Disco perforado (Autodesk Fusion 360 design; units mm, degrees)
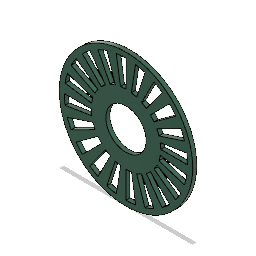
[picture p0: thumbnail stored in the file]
sketch "Sketch1"
  circle C1 centre (0, 0) radius 7.5
  circle C2 centre (0, 0) radius 25
  dimension "d1" diameter C1 = 15
  dimension "d2" diameter C2 = 50
extrude "Extrude1" new body sketch "Sketch1" blind 2
sketch "Sketch2"
  line L1 (25, 0) -> (0, 0)
  line L2 (25, 0) -> (0, 0)
  line L3 (25, 0) -> (0, 0)
  line L4 (24.6922, 3.9109) -> (0, 0)
  line L5 (23.7764, 7.7254) -> (0, 0)
  line L6 (20.2254, 14.6946) -> (0, 0)
  line L7 (22.2752, 11.3498) -> (0, 0)
  line L8 (23.7764, 7.7254) -> (0, 0)
  line L9 (14.6946, 20.2254) -> (0, 0)
  line L10 (17.6777, 17.6777) -> (0, 0)
  line L11 (20.2254, 14.6946) -> (0, 0)
  line L12 (7.7254, 23.7764) -> (0, 0)
  line L13 (11.3498, 22.2752) -> (0, 0)
  line L14 (14.6946, 20.2254) -> (0, 0)
  line L15 (0, 25) -> (0, 0)
  line L16 (3.9109, 24.6922) -> (0, 0)
  line L17 (7.7254, 23.7764) -> (0, 0)
  line L18 (0, 25) -> (0, 0)
  line L19 (-3.9109, 24.6922) -> (0, 0)
  line L20 (-7.7254, 23.7764) -> (0, 0)
  line L21 (-11.3498, 22.2752) -> (0, 0)
  line L22 (-14.6946, 20.2254) -> (0, 0)
  line L23 (-17.6777, 17.6777) -> (0, 0)
  line L24 (-20.2254, 14.6946) -> (0, 0)
  line L25 (-22.2752, 11.3498) -> (0, 0)
  line L26 (-23.7764, 7.7254) -> (0, 0)
  line L27 (-24.6922, 3.9109) -> (0, 0)
  line L28 (-25, 0) -> (0, 0)
  line L29 (-25, 0) -> (0, 0)
  line L30 (-24.6922, -3.9109) -> (0, 0)
  line L31 (-23.7764, -7.7254) -> (0, 0)
  line L32 (-22.2752, -11.3498) -> (0, 0)
  line L33 (-20.2254, -14.6946) -> (0, 0)
  line L34 (-17.6777, -17.6777) -> (0, 0)
  line L35 (-14.6946, -20.2254) -> (0, 0)
  line L36 (-11.3498, -22.2752) -> (0, 0)
  line L37 (-7.7254, -23.7764) -> (0, 0)
  line L38 (-3.9109, -24.6922) -> (0, 0)
  line L39 (0, -25) -> (0, 0)
  line L40 (0, -25) -> (0, 0)
  line L41 (3.9109, -24.6922) -> (0, 0)
  line L42 (7.7254, -23.7764) -> (0, 0)
  line L43 (11.3498, -22.2752) -> (0, 0)
  line L44 (14.6946, -20.2254) -> (0, 0)
  line L45 (17.6777, -17.6777) -> (0, 0)
  line L46 (20.2254, -14.6946) -> (0, 0)
  line L47 (22.2752, -11.3498) -> (0, 0)
  line L48 (23.7764, -7.7254) -> (0, 0)
  line L49 (24.6922, -3.9109) -> (0, 0)
  line L50 (25, 0) -> (0, 0)
  circle C1 centre (0, 0) radius 25
  arc A1 centre (0, 0) radius 23 clockwise from (22.7168, 3.598) to (23, 0)
  arc A2 centre (0, 0) radius 13 clockwise from (12.8399, 2.0336) to (13, 0)
  arc A3 centre (0, 0) radius 13 clockwise from (11.5831, 5.9019) to (12.3637, 4.0172)
  arc A4 centre (0, 0) radius 23 clockwise from (20.4932, 10.4418) to (21.8743, 7.1074)
  arc A5 centre (0, 0) radius 13 clockwise from (9.1924, 9.1924) to (10.5172, 7.6412)
  arc A6 centre (0, 0) radius 23 clockwise from (16.2635, 16.2635) to (18.6074, 13.5191)
  arc A7 centre (0, 0) radius 13 clockwise from (5.9019, 11.5831) to (7.6412, 10.5172)
  arc A8 centre (0, 0) radius 23 clockwise from (10.4418, 20.4932) to (13.5191, 18.6074)
  arc A9 centre (0, 0) radius 13 clockwise from (2.0336, 12.8399) to (4.0172, 12.3637)
  arc A10 centre (0, 0) radius 23 clockwise from (3.598, 22.7168) to (7.1074, 21.8743)
  arc A11 centre (0, 0) radius 13 clockwise from (-2.0336, 12.8399) to (0, 13)
  arc A12 centre (0, 0) radius 13 clockwise from (-5.9019, 11.5831) to (-4.0172, 12.3637)
  arc A13 centre (0, 0) radius 13 clockwise from (-9.1924, 9.1924) to (-7.6412, 10.5172)
  arc A14 centre (0, 0) radius 13 clockwise from (-11.5831, 5.9019) to (-10.5172, 7.6412)
  arc A15 centre (0, 0) radius 13 clockwise from (-12.8399, 2.0336) to (-12.3637, 4.0172)
  arc A16 centre (0, 0) radius 23 clockwise from (-3.598, 22.7168) to (0, 23)
  arc A17 centre (0, 0) radius 23 clockwise from (-10.4418, 20.4932) to (-7.1074, 21.8743)
  arc A18 centre (0, 0) radius 23 clockwise from (-16.2635, 16.2635) to (-13.5191, 18.6074)
  arc A19 centre (0, 0) radius 23 clockwise from (-20.4932, 10.4418) to (-18.6074, 13.5191)
  arc A20 centre (0, 0) radius 23 clockwise from (-22.7168, 3.598) to (-21.8743, 7.1074)
  arc A21 centre (0, 0) radius 13 clockwise from (-12.8399, -2.0336) to (-13, 0)
  arc A22 centre (0, 0) radius 13 clockwise from (-11.5831, -5.9019) to (-12.3637, -4.0172)
  arc A23 centre (0, 0) radius 13 clockwise from (-9.1924, -9.1924) to (-10.5172, -7.6412)
  arc A24 centre (0, 0) radius 13 clockwise from (-5.9019, -11.5831) to (-7.6412, -10.5172)
  arc A25 centre (0, 0) radius 13 clockwise from (-2.0336, -12.8399) to (-4.0172, -12.3637)
  arc A26 centre (0, 0) radius 23 clockwise from (-22.7168, -3.598) to (-23, 0)
  arc A27 centre (0, 0) radius 23 clockwise from (-20.4932, -10.4418) to (-21.8743, -7.1074)
  arc A28 centre (0, 0) radius 23 clockwise from (-16.2635, -16.2635) to (-18.6074, -13.5191)
  arc A29 centre (0, 0) radius 23 clockwise from (-10.4418, -20.4932) to (-13.5191, -18.6074)
  arc A30 centre (0, 0) radius 23 clockwise from (-3.598, -22.7168) to (-7.1074, -21.8743)
  arc A31 centre (0, 0) radius 13 clockwise from (2.0336, -12.8399) to (0, -13)
  arc A32 centre (0, 0) radius 13 clockwise from (5.9019, -11.5831) to (4.0172, -12.3637)
  arc A33 centre (0, 0) radius 13 clockwise from (9.1924, -9.1924) to (7.6412, -10.5172)
  arc A34 centre (0, 0) radius 13 clockwise from (11.5831, -5.9019) to (10.5172, -7.6412)
  arc A35 centre (0, 0) radius 13 clockwise from (12.8399, -2.0336) to (12.3637, -4.0172)
  arc A36 centre (0, 0) radius 23 clockwise from (3.598, -22.7168) to (0, -23)
  arc A37 centre (0, 0) radius 23 clockwise from (10.4418, -20.4932) to (7.1074, -21.8743)
  arc A38 centre (0, 0) radius 23 clockwise from (16.2635, -16.2635) to (13.5191, -18.6074)
  arc A39 centre (0, 0) radius 23 clockwise from (20.4932, -10.4418) to (18.6074, -13.5191)
  arc A40 centre (0, 0) radius 23 clockwise from (22.7168, -3.598) to (21.8743, -7.1074)
  circle C2 centre (0, 0) radius 7.5
pcb "PCB" sketch "Sketch2" BoardHeight 1.57 OffsetX 0 OffsetY 0 OffsetZ 0 AngleZ 0
extrude "Extrude2" cut sketch "Sketch2" profile of L1 L2 L3 L4 L5 A1 A2 L6 L7 L8 A3 A4 L9 L10 L11 A5 A6 L12 L13 L14 A7 A8 L15 L16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 blind 3
sketch "Sketch3"
  circle C1 centre (0, 0) radius 10
  circle C2 centre (-10, 0) radius 1.5
  circle C3 centre (5, -8.6603) radius 1.5
  circle C4 centre (5, 8.6603) radius 1.5
  dimension "d7" diameter C2 = 3
  dimension "d8" diameter C3 = 3
  dimension "d9" diameter C4 = 3
sketch "Sketch4"
pcb "e0997e98-fd7f-0000-109b-7e98fd7f0000" BoardHeight 1.57
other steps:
extrude "Extrude1" new body sketch "Sketch2" blind 1.57 bodies "Board"
create_component "CreateComponent1" sketch "Sketch2"
as_built_joint "As-built1"
named bodies: "Board"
